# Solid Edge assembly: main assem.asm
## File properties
Author: Robert a Rhodes jr
Template: Normal.asm
Last saved by: CADCIM
Revision: 20
Application: Solid Edge
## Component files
master rod.par
piston.par
piston pin.par
arti subassm.asm
piston pin plug.par
piston ring.par
master rod bearing.par
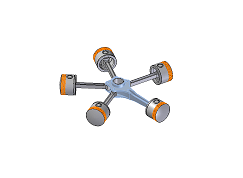
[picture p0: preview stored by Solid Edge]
